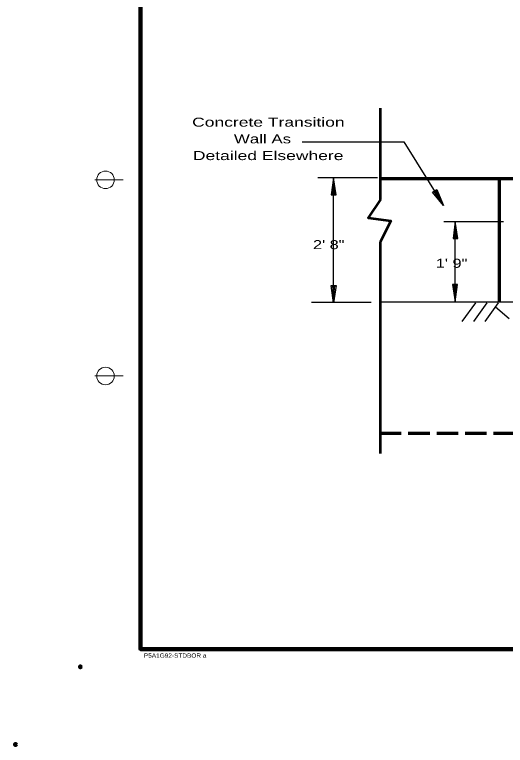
# Model space of a CAD drawing. Extents: x 856.9 to 891.7, y -2278.5 to -2254.7.
# Drawn here: x 856.9 to 863.91, y -2278.54 to -2268.1 of the extents above; entities that cross this region are included whole.
import ezdxf

# ---------------------------------------------------------------- set-up
doc = ezdxf.new("R2010")
doc.units = 0
doc.header["$LTSCALE"] = 0.051
doc.header["$PDMODE"] = 32
doc.header["$PDSIZE"] = 0.0255
doc.linetypes.add('LONG_DASHED', pattern=[7.5, 6, -1.5])
doc.layers.add('1', color=7, linetype='Continuous', lineweight=70)
doc.layers.add('3', color=7, linetype='Continuous', lineweight=40)

msp = doc.modelspace()

# ---------------------------------------------------------------- linework, layer by layer
at = {"layer": '1', "lineweight": 53}
for p, q in [((862.12625, -2270.742), (862.12625, -2269.43992)), ((862.12625, -2274.37225), (862.12625, -2271.34517))]:
    msp.add_line(p, q, dxfattribs=at)
at = {"layer": '1', "lineweight": 25}
for p, q in [((861.00808, -2269.9225), (862.45833, -2269.9225)), ((862.45833, -2269.9225), (862.99767, -2270.79175)), ((861.22858, -2270.43083), (862.08, -2270.43083)), ((861.45192, -2272.1915), (861.45192, -2270.57875)), ((863.02933, -2271.05683), (863.88075, -2271.05683)), ((863.192, -2272.20317), (863.192, -2271.05683)), ((861.14133, -2272.21025), (861.99275, -2272.21025)), ((862.12625, -2272.20317), (882.07667, -2272.20317)), ((863.292, -2272.48467), (863.48333, -2272.21883)), ((863.45583, -2272.48467), (863.647, -2272.21883)), ((863.6195, -2272.48467), (863.81075, -2272.21883)), ((863.96075, -2272.44933), (863.76567, -2272.28183))]:
    msp.add_line(p, q, dxfattribs=at)
at = {"layer": '1'}
for p, q in [((862.12625, -2270.44258), (863.81658, -2270.44258)), ((863.80467, -2270.44258), (865.43792, -2270.45175)), ((863.81658, -2270.44258), (863.81658, -2272.2085))]:
    msp.add_line(p, q, dxfattribs=at)
at = {"layer": '1', "lineweight": 13}
msp.add_line((863.02933, -2272.20317), (863.88075, -2272.20317), dxfattribs=at)
at = {"layer": '1', "linetype": 'LONG_DASHED'}
msp.add_line((862.115, -2274.08083), (865.61775, -2274.08083), dxfattribs=at)
at = {"layer": '1', "lineweight": 25}
for points in [[(861.45192, -2270.43458), (861.42025, -2270.679), (861.49042, -2270.679)], [(863.02433, -2270.83108), (862.8685, -2270.63975), (862.92792, -2270.60308)], [(863.192, -2271.05683), (863.16033, -2271.30125), (863.2305, -2271.30125)], [(861.45192, -2272.21842), (861.42025, -2271.974), (861.49042, -2271.974)], [(863.192, -2272.20317), (863.22325, -2271.95883), (863.15308, -2271.95883)]]:
    msp.add_lwpolyline(points, close=True, dxfattribs=at)
for points in [[(861.43808, -2270.679), (861.45192, -2270.49558), (861.47258, -2270.679)], [(861.4465, -2270.679), (861.45383, -2270.59192), (861.46425, -2270.679)], [(862.8835, -2270.63058), (862.99233, -2270.77917), (862.913, -2270.61233)], [(862.89075, -2270.62617), (862.94308, -2270.69675), (862.90575, -2270.61683)], [(863.17817, -2271.30125), (863.192, -2271.11783), (863.21267, -2271.30125)], [(863.18658, -2271.30125), (863.19392, -2271.21417), (863.20433, -2271.30125)], [(861.43808, -2271.974), (861.45192, -2272.15742), (861.47258, -2271.974)], [(861.4465, -2271.974), (861.45383, -2272.06108), (861.46425, -2271.974)], [(863.20558, -2271.95883), (863.192, -2272.14225), (863.17092, -2271.95883)], [(863.19708, -2271.95883), (863.18983, -2272.04592), (863.17942, -2271.95883)]]:
    msp.add_lwpolyline(points, dxfattribs=at)
at = {"layer": '1', "lineweight": 53}
msp.add_lwpolyline([(862.12625, -2270.742), (861.94808, -2271.00642), (862.27167, -2271.04842), (862.12625, -2271.34517)], dxfattribs=at)
at = {"layer": '1'}
for p in [(857.84133, -2277.41467), (856.91592, -2278.52408)]:
    msp.add_point(p, dxfattribs=at)
at = {"layer": '3', "lineweight": 158}
msp.add_line((858.7, -2256.16333), (858.7, -2277.16333), dxfattribs=at)
at = {"layer": '3', "lineweight": 13}
for p, q in [((858.45, -2270.46333), (858.05, -2270.46333)), ((858.45, -2273.26333), (858.05, -2273.26333))]:
    msp.add_line(p, q, dxfattribs=at)
at = {"layer": '3', "lineweight": 158}
msp.add_lwpolyline([(891.2, -2256.16333), (891.2, -2277.16333), (858.7, -2277.16333)], dxfattribs=at)
at = {"layer": '3', "lineweight": 13}
for centre in [(858.2, -2270.46333), (858.2, -2273.26333)]:
    msp.add_circle(centre, 0.125, dxfattribs=at)
at = {"layer": '3'}
msp.add_point((858.7, -2277.16333), dxfattribs=at)

# ---------------------------------------------------------------- texts
at = {"layer": '1'}
for s, width, p in [('Concrete Transition', 1.45, (859.4365, -2269.70417)), ('Wall As', 1.4, (860.03258, -2269.94283)), ('Detailed Elsewhere', 1.45, (859.44733, -2270.1815)), ('2\' 8"', 1.35, (861.16108, -2271.45292)), ('1\' 9"', 1.35, (862.91442, -2271.71883))]:
    msp.add_text(s, height=0.1286, dxfattribs=dict(at, width=width)).set_placement(p)
at = {"layer": '3', "width": 1.15}
msp.add_text('P5A1G92-STDBOR a', height=0.06, dxfattribs=at).set_placement((858.748, -2277.28433))

doc.saveas('drawing.dxf')
